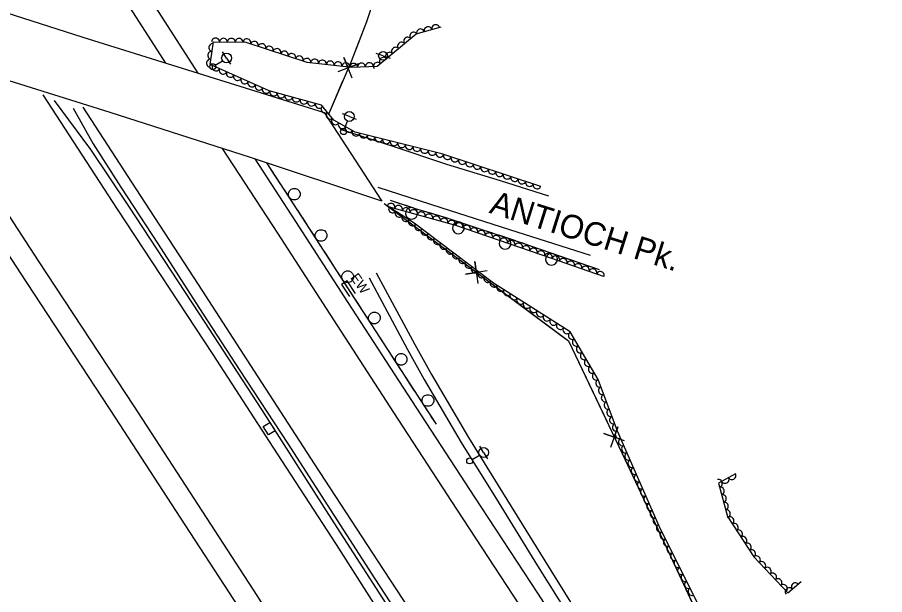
# Model space of a CAD drawing. Extents: x 1746719 to 1766531, y 631721 to 662391.
# Drawn here: x 1758988.5 to 1759429.7, y 642813.8 to 643107.3 of the extents above; entities that cross this region are included whole.
import ezdxf

# ---------------------------------------------------------------- set-up
doc = ezdxf.new("R2010")
doc.units = 0
for name, color, linetype in [('SURVEY - AERIAL SURVEY - Photo Control - Points - Elevations', 7, 'Continuous'), ('SURVEY - AERIAL SURVEY - Photo Control - Points - Numbers', 7, 'Continuous'), ('SURVEY - AERIAL SURVEY - Photo Control with Text', 7, 'Continuous'), ('SURVEY - CENTERLINE - Existing Roads - Development', 7, 'Continuous'), ('SURVEY - CENTERLINE - Existing Roads Curve Text', 7, 'Continuous'), ('SURVEY - CENTERLINE - Existing Roads Text', 7, 'Continuous'), ('SURVEY - CENTERLINE - Preliminary - Development', 7, 'Continuous'), ('SURVEY - CENTERLINE - Preliminary Curve Text', 7, 'Continuous'), ('SURVEY - CONTROL - Points - Numbers', 7, 'Continuous')]:
    doc.layers.add(name, color=color, linetype=linetype)

msp = doc.modelspace()

# ---------------------------------------------------------------- linework, layer by layer
at = {"layer": 'SURVEY - AERIAL SURVEY - Photo Control - Points - Elevations'}
for points in [[(1758528.06, 643931.93), (1758563.85, 643876.61), (1758601.12, 643819.25), (1758634.52, 643767.49), (1758665.16, 643720.35), (1758703.51, 643661.29), (1758738.55, 643607.32), (1758780.47, 643542.02), (1758810.94, 643495.12), (1758838.28, 643453.17), (1758866.99, 643408.66), (1758892.36, 643369.61), (1758923.55, 643321.11), (1758957.87, 643268.54), (1758994.04, 643213.01), (1759028.02, 643160.29), (1759080.26, 643078.92)], [(1758518.82, 643925.96), (1758554.62, 643870.63), (1758591.89, 643813.27), (1758625.29, 643761.51), (1758655.94, 643714.35), (1758694.29, 643655.3), (1758729.31, 643601.35), (1758771.23, 643536.05), (1758801.72, 643489.13), (1758829.05, 643447.19), (1758857.76, 643402.68), (1758883.12, 643363.64), (1758914.32, 643315.13), (1758948.66, 643262.53), (1758984.81, 643207.03), (1759018.77, 643154.33), (1759063.92, 643084.02)], [(1758911.54, 643097.78), (1758989.93, 642977.45), (1759038.48, 642903.58), (1759068.99, 642856.62), (1759101.06, 642807.38), (1759127.09, 642766.38), (1759158.82, 642717.62), (1759188.78, 642671.16), (1759215.73, 642628.82), (1759243.37, 642584.64)], [(1758928.02, 643092.63), (1758999.13, 642983.47), (1759047.68, 642909.6), (1759078.21, 642862.62), (1759110.31, 642813.33), (1759136.34, 642772.33), (1759168.05, 642723.6), (1759198.04, 642677.1), (1759225.03, 642634.69), (1759251.44, 642592.47), (1759258.89, 642580.68)], [(1759001.41, 643067.92), (1759039.3, 643009.76), (1759087.86, 642935.86), (1759118.45, 642888.8), (1759150.69, 642839.29), (1759176.72, 642798.29), (1759208.34, 642749.7), (1759238.46, 642702.99), (1759265.63, 642660.31), (1759292.08, 642618.02), (1759319.51, 642574.62)], [(1759021.72, 643061.55), (1759051.04, 643016.68), (1759080.55, 642971.41), (1759107.16, 642930.21), (1759139.57, 642880.23), (1759171.78, 642830.99), (1759203.62, 642782.41), (1759232.48, 642737.67), (1759263.95, 642689.2), (1759295.27, 642641.6), (1759332.64, 642583.53)], [(1759258.95, 643016.38), (1759234.29, 643024.12), (1759206.97, 643032.5), (1759180.19, 643041.4), (1759152.9, 643050.18)], [(1759092.74, 643040.6), (1759120.81, 642997.54), (1759147.46, 642956.29), (1759179.8, 642906.42), (1759211.94, 642857.29), (1759243.86, 642808.57), (1759272.78, 642763.75), (1759304.12, 642715.46), (1759335.5, 642667.78), (1759373, 642609.52)], [(1759109.35, 643035.26), (1759130.04, 643003.53), (1759156.69, 642962.27), (1759189.01, 642912.43), (1759221.14, 642863.31), (1759253.09, 642814.57), (1759282.01, 642769.72), (1759313.33, 642721.48), (1759344.72, 642673.78), (1759382.25, 642615.47)], [(1759280.06, 642986.24), (1759239.01, 642999.29), (1759204.06, 643010.38), (1759172.11, 643020.76)]]:
    msp.add_lwpolyline(points, dxfattribs=at)
at = {"layer": 'SURVEY - AERIAL SURVEY - Photo Control - Points - Numbers'}
for points in [[(1759007.19, 643064.96), (1759025.66, 643040.03), (1759044.99, 643011.2), (1759080.91, 642956.61), (1759112.63, 642907.86), (1759149.44, 642850.31), (1759187.39, 642791.73), (1759215.17, 642749.46), (1759246.32, 642701.23), (1759270.84, 642663.44), (1759296.65, 642624.73), (1759310.14, 642601.55), (1759323.65, 642577.03)], [(1759016.86, 643061.11), (1759027.02, 643042.95), (1759041.14, 643020.93), (1759060.14, 642992.04), (1759080.88, 642959.71), (1759101.74, 642927.76), (1759125.98, 642890.82), (1759149.43, 642854.16), (1759170.35, 642821.89), (1759192.85, 642787.19), (1759216.64, 642750.69), (1759240.52, 642713.73), (1759263.06, 642678.75), (1759290.15, 642637.06), (1759302.4, 642618.23), (1759316.38, 642598.71), (1759329.6, 642580.54)], [(1759201.66, 642900.4), (1759192.36, 642914.61), (1759160.05, 642964.44), (1759133.4, 643005.71), (1759115.45, 643033.24)], [(1759115.7, 643032.85), (1759115.45, 643033.24)], [(1759120.01, 643026.23), (1759117.45, 643030.17)], [(1759122.58, 643022.3), (1759120.01, 643026.23)], [(1759129.35, 643011.91), (1759124.33, 643019.62)], [(1759178.1, 643014.34), (1759190.9, 643010.16), (1759206.92, 643005.4), (1759244.65, 642992.85), (1759284.43, 642979.03)], [(1759178.1, 643014.34), (1759182.57, 643012.88)], [(1759185.61, 643011.88), (1759190.9, 643010.16), (1759194.39, 643009.12)], [(1759133.67, 643005.29), (1759133.4, 643005.71), (1759131.1, 643009.23)], [(1759197.46, 643008.21), (1759201.96, 643006.87)], [(1759201.96, 643006.87), (1759206.47, 643005.54)], [(1759136.22, 643001.34), (1759133.67, 643005.29)], [(1759209.51, 643004.54), (1759218.24, 643001.64)], [(1759142.94, 642990.93), (1759137.95, 642998.66)], [(1759221.28, 643000.63), (1759225.74, 642999.14)], [(1759225.74, 642999.14), (1759230.2, 642997.66)], [(1759233.23, 642996.65), (1759241.96, 642993.75)], [(1759245, 642992.73), (1759249.44, 642991.19)], [(1759249.44, 642991.19), (1759253.88, 642989.65)], [(1759256.9, 642988.6), (1759265.59, 642985.58)], [(1759147.23, 642984.29), (1759144.68, 642988.24)], [(1759149.78, 642980.34), (1759147.23, 642984.29)], [(1759268.61, 642984.53), (1759273.05, 642982.98)], [(1759273.05, 642982.98), (1759277.49, 642981.44)], [(1759280.51, 642980.39), (1759284.43, 642979.03)], [(1759156.51, 642969.93), (1759151.51, 642977.66)], [(1759160.79, 642963.29), (1759160.05, 642964.44), (1759158.24, 642967.24)], [(1759163.35, 642959.35), (1759160.79, 642963.29)], [(1759170.1, 642948.94), (1759165.09, 642956.66)], [(1759174.4, 642942.32), (1759171.84, 642946.26)], [(1759176.95, 642938.37), (1759174.4, 642942.32)], [(1759183.7, 642927.97), (1759178.7, 642935.69)], [(1759188, 642921.34), (1759185.44, 642925.28)], [(1759190.56, 642917.4), (1759188, 642921.34)], [(1759197.33, 642907.01), (1759192.36, 642914.61), (1759192.3, 642914.71)], [(1759201.66, 642900.4), (1759199.09, 642904.34)]]:
    msp.add_lwpolyline(points, dxfattribs=at)
for centre, start, end in [((1759129.38, 643017.36), 326.3727, 326.3587), ((1759189.01, 643007.62), 185.178, 185.164), ((1759212.89, 643000.26), 184.8727, 184.8588), ((1759142.99, 642996.38), 326.1247, 326.1107), ((1759236.61, 642992.37), 184.8727, 184.8588), ((1759260.22, 642984.27), 184.1027, 184.0887), ((1759156.55, 642975.38), 326.1247, 326.1107), ((1759170.14, 642954.4), 326.2333, 326.2193), ((1759183.74, 642933.42), 326.2333, 326.2193), ((1759197.35, 642912.47), 326.4591, 326.4451)]:
    msp.add_arc(centre, 3, start, end, dxfattribs=at)
at = {"layer": 'SURVEY - AERIAL SURVEY - Photo Control with Text'}
for points in [[(1759254.76, 643021.35), (1759204.49, 643037.81), (1759160.4, 643048.88), (1759149.45, 643055.05), (1759143.16, 643062.68), (1759116.67, 643069.84), (1759086.54, 643083.23), (1759088.27, 643094.82), (1759104.79, 643094.58), (1759135.7, 643084.53), (1759158.72, 643081.94), (1759171.48, 643082.41), (1759191.44, 643098.92), (1759204.1, 643102.39)], [(1759429.72, 642645.24), (1759395.51, 642683.74), (1759381.02, 642706.41), (1759361.81, 642748.55), (1759341.14, 642796.23), (1759314.98, 642848.6), (1759293.78, 642896.97), (1759283.92, 642923.22), (1759269.67, 642947.31), (1759230.71, 642972.18), (1759190.33, 643002.56), (1759177.19, 643011.19), (1759211.36, 643001.58), (1759260.17, 642984.88), (1759286.57, 642975.65)], [(1759353.87, 642875.13), (1759345.13, 642870.47), (1759349.69, 642853.56), (1759363.17, 642833.03), (1759380.39, 642814.76), (1759387.28, 642820.39)]]:
    msp.add_lwpolyline(points, dxfattribs=at)
for centre, major_axis in [((1759201.28, 643101.61), (1.93, 0.53)), ((1759190.06, 643097.78), (1.54, 1.27)), ((1759193.57, 643099.5), (1.93, 0.53)), ((1759197.42, 643100.56), (1.93, 0.53)), ((1759089.34, 643094.8), (2, -0.03)), ((1759093.34, 643094.74), (2, -0.03)), ((1759097.34, 643094.69), (2, -0.03)), ((1759101.33, 643094.63), (2, -0.03)), ((1759105.31, 643094.41), (1.9, -0.62)), ((1759109.11, 643093.17), (1.9, -0.62)), ((1759183.89, 643092.68), (1.54, 1.27)), ((1759186.97, 643095.23), (1.54, 1.27)), ((1759087.25, 643087.96), (0.3, 1.98)), ((1759087.84, 643091.91), (0.3, 1.98)), ((1759112.92, 643091.94), (1.9, -0.62)), ((1759116.72, 643090.7), (1.9, -0.62)), ((1759120.52, 643089.46), (1.9, -0.62)), ((1759124.33, 643088.23), (1.9, -0.62)), ((1759180.81, 643090.13), (1.54, 1.27)), ((1759086.65, 643084), (0.3, 1.98)), ((1759128.13, 643086.99), (1.9, -0.62)), ((1759131.94, 643085.75), (1.9, -0.62)), ((1759135.74, 643084.53), (1.99, -0.22)), ((1759139.72, 643084.08), (1.99, -0.22)), ((1759143.69, 643083.63), (1.99, -0.22)), ((1759174.65, 643085.03), (1.54, 1.27)), ((1759177.73, 643087.58), (1.54, 1.27)), ((1759089.48, 643081.92), (-1.83, 0.81)), ((1759093.14, 643080.3), (-1.83, 0.81)), ((1759147.67, 643083.18), (1.99, -0.22)), ((1759151.64, 643082.73), (1.99, -0.22)), ((1759155.62, 643082.29), (1.99, -0.22)), ((1759159.6, 643081.97), (2, 0.07)), ((1759163.59, 643082.12), (2, 0.07)), ((1759167.59, 643082.27), (2, 0.07)), ((1759171.56, 643082.48), (1.54, 1.27)), ((1759096.79, 643078.67), (-1.83, 0.81)), ((1759100.45, 643077.05), (-1.83, 0.81)), ((1759104.1, 643075.42), (-1.83, 0.81)), ((1759107.76, 643073.8), (-1.83, 0.81)), ((1759111.41, 643072.17), (-1.83, 0.81)), ((1759115.07, 643070.55), (-1.83, 0.81)), ((1759118.84, 643069.25), (-1.93, 0.52)), ((1759122.7, 643068.21), (-1.93, 0.52)), ((1759126.56, 643067.16), (-1.93, 0.52)), ((1759130.42, 643066.12), (-1.93, 0.52)), ((1759134.29, 643065.08), (-1.93, 0.52)), ((1759138.15, 643064.03), (-1.93, 0.52)), ((1759142.01, 643062.99), (-1.93, 0.52)), ((1759144.95, 643060.51), (-1.27, 1.54)), ((1759147.49, 643057.42), (-1.27, 1.54)), ((1759150.25, 643054.6), (-1.74, 0.98)), ((1759153.74, 643052.63), (-1.74, 0.98)), ((1759157.22, 643050.67), (-1.74, 0.98)), ((1759160.74, 643048.79), (-1.94, 0.49)), ((1759164.62, 643047.82), (-1.94, 0.49)), ((1759168.5, 643046.84), (-1.94, 0.49)), ((1759172.38, 643045.87), (-1.94, 0.49)), ((1759176.26, 643044.9), (-1.94, 0.49)), ((1759180.14, 643043.92), (-1.94, 0.49)), ((1759184.02, 643042.95), (-1.94, 0.49)), ((1759187.9, 643041.98), (-1.94, 0.49)), ((1759191.78, 643041), (-1.94, 0.49)), ((1759195.66, 643040.03), (-1.94, 0.49)), ((1759199.54, 643039.05), (-1.94, 0.49)), ((1759203.42, 643038.08), (-1.94, 0.49)), ((1759207.24, 643036.91), (-1.9, 0.62)), ((1759211.04, 643035.67), (-1.9, 0.62)), ((1759214.84, 643034.42), (-1.9, 0.62)), ((1759218.64, 643033.18), (-1.9, 0.62)), ((1759222.44, 643031.93), (-1.9, 0.62)), ((1759226.25, 643030.69), (-1.9, 0.62)), ((1759230.05, 643029.44), (-1.9, 0.62)), ((1759233.85, 643028.2), (-1.9, 0.62)), ((1759237.65, 643026.95), (-1.9, 0.62)), ((1759241.45, 643025.71), (-1.9, 0.62)), ((1759245.25, 643024.47), (-1.9, 0.62)), ((1759249.05, 643023.22), (-1.9, 0.62)), ((1759252.86, 643021.98), (-1.9, 0.62)), ((1759178.59, 643010.8), (1.93, -0.54)), ((1759179.31, 643009.8), (-1.67, 1.1)), ((1759182.44, 643009.72), (1.93, -0.54)), ((1759186.29, 643008.63), (1.93, -0.54)), ((1759182.66, 643007.6), (-1.67, 1.1)), ((1759186, 643005.4), (-1.67, 1.1)), ((1759190.14, 643007.55), (1.93, -0.54)), ((1759193.99, 643006.47), (1.93, -0.54)), ((1759197.85, 643005.39), (1.93, -0.54)), ((1759201.7, 643004.3), (1.93, -0.54)), ((1759189.34, 643003.21), (-1.67, 1.1)), ((1759192.58, 643000.87), (-1.6, 1.2)), ((1759205.55, 643003.22), (1.93, -0.54)), ((1759209.4, 643002.14), (1.93, -0.54)), ((1759213.22, 643000.95), (1.89, -0.65)), ((1759217, 642999.66), (1.89, -0.65)), ((1759195.78, 642998.46), (-1.6, 1.2)), ((1759198.98, 642996.06), (-1.6, 1.2)), ((1759220.78, 642998.36), (1.89, -0.65)), ((1759224.57, 642997.06), (1.89, -0.65)), ((1759228.35, 642995.77), (1.89, -0.65)), ((1759202.17, 642993.65), (-1.6, 1.2)), ((1759232.14, 642994.47), (1.89, -0.65)), ((1759235.92, 642993.18), (1.89, -0.65)), ((1759239.71, 642991.88), (1.89, -0.65)), ((1759243.49, 642990.59), (1.89, -0.65)), ((1759205.37, 642991.25), (-1.6, 1.2)), ((1759208.57, 642988.84), (-1.6, 1.2)), ((1759247.28, 642989.29), (1.89, -0.65)), ((1759251.06, 642987.99), (1.89, -0.65)), ((1759254.84, 642986.7), (1.89, -0.65)), ((1759211.76, 642986.44), (-1.6, 1.2)), ((1759214.96, 642984.03), (-1.6, 1.2)), ((1759258.63, 642985.4), (1.89, -0.65)), ((1759262.41, 642984.09), (1.89, -0.66)), ((1759266.18, 642982.77), (1.89, -0.66)), ((1759218.16, 642981.63), (-1.6, 1.2)), ((1759221.35, 642979.22), (-1.6, 1.2)), ((1759269.96, 642981.46), (1.89, -0.66)), ((1759273.74, 642980.14), (1.89, -0.66)), ((1759277.51, 642978.82), (1.89, -0.66)), ((1759281.29, 642977.5), (1.89, -0.66)), ((1759224.55, 642976.82), (-1.6, 1.2)), ((1759227.75, 642974.41), (-1.6, 1.2)), ((1759285.07, 642976.18), (1.89, -0.66)), ((1759230.95, 642972.03), (-1.69, 1.08)), ((1759234.33, 642969.87), (-1.69, 1.08)), ((1759237.7, 642967.72), (-1.69, 1.08)), ((1759241.07, 642965.57), (-1.69, 1.08)), ((1759244.44, 642963.42), (-1.69, 1.08)), ((1759247.81, 642961.26), (-1.69, 1.08)), ((1759251.18, 642959.11), (-1.69, 1.08)), ((1759254.55, 642956.96), (-1.69, 1.08)), ((1759257.92, 642954.81), (-1.69, 1.08)), ((1759261.3, 642952.65), (-1.69, 1.08)), ((1759264.67, 642950.5), (-1.69, 1.08)), ((1759268.04, 642948.35), (-1.69, 1.08)), ((1759270.72, 642945.53), (-1.02, 1.72)), ((1759272.76, 642942.09), (-1.02, 1.72)), ((1759274.8, 642938.64), (-1.02, 1.72)), ((1759276.83, 642935.2), (-1.02, 1.72)), ((1759278.87, 642931.76), (-1.02, 1.72)), ((1759280.91, 642928.32), (-1.02, 1.72)), ((1759282.94, 642924.87), (-1.02, 1.72)), ((1759284.65, 642921.27), (-0.7, 1.87)), ((1759286.06, 642917.53), (-0.7, 1.87)), ((1759287.46, 642913.78), (-0.7, 1.87)), ((1759288.87, 642910.04), (-0.7, 1.87)), ((1759290.27, 642906.29), (-0.7, 1.87)), ((1759291.68, 642902.55), (-0.7, 1.87)), ((1759293.09, 642898.8), (-0.7, 1.87)), ((1759294.59, 642895.1), (-0.8, 1.83)), ((1759296.2, 642891.44), (-0.8, 1.83)), ((1759297.81, 642887.77), (-0.8, 1.83)), ((1759299.41, 642884.11), (-0.8, 1.83)), ((1759301.02, 642880.45), (-0.8, 1.83)), ((1759302.63, 642876.78), (-0.8, 1.83)), ((1759304.23, 642873.12), (-0.8, 1.83)), ((1759352.1, 642874.19), (-1.76, -0.94)), ((1759305.84, 642869.46), (-0.8, 1.83)), ((1759345.16, 642870.37), (0.52, -1.93)), ((1759348.57, 642872.3), (-1.76, -0.94)), ((1759307.44, 642865.79), (-0.8, 1.83)), ((1759346.2, 642866.51), (0.52, -1.93)), ((1759347.24, 642862.64), (0.52, -1.93)), ((1759309.05, 642862.13), (-0.8, 1.83)), ((1759348.28, 642858.78), (0.52, -1.93)), ((1759310.66, 642858.47), (-0.8, 1.83)), ((1759312.26, 642854.8), (-0.8, 1.83)), ((1759349.32, 642854.92), (0.52, -1.93)), ((1759313.87, 642851.14), (-0.8, 1.83)), ((1759351.11, 642851.39), (1.1, -1.67)), ((1759315.53, 642847.5), (-0.89, 1.79)), ((1759353.3, 642848.05), (1.1, -1.67)), ((1759317.32, 642843.93), (-0.89, 1.79)), ((1759355.5, 642844.71), (1.1, -1.67)), ((1759357.7, 642841.36), (1.1, -1.67)), ((1759319.11, 642840.35), (-0.89, 1.79)), ((1759320.89, 642836.77), (-0.89, 1.79)), ((1759359.89, 642838.02), (1.1, -1.67)), ((1759322.68, 642833.19), (-0.89, 1.79)), ((1759362.09, 642834.67), (1.1, -1.67)), ((1759324.47, 642829.61), (-0.89, 1.79)), ((1759364.56, 642831.55), (1.37, -1.46)), ((1759367.3, 642828.64), (1.37, -1.46)), ((1759326.25, 642826.03), (-0.89, 1.79)), ((1759370.05, 642825.73), (1.37, -1.46)), ((1759328.04, 642822.45), (-0.89, 1.79)), ((1759329.83, 642818.88), (-0.89, 1.79)), ((1759372.79, 642822.82), (1.37, -1.46)), ((1759375.54, 642819.91), (1.37, -1.46)), ((1759331.62, 642815.3), (-0.89, 1.79)), ((1759378.28, 642817), (1.37, -1.46)), ((1759381.1, 642815.34), (1.55, 1.27)), ((1759384.2, 642817.87), (1.55, 1.27))]:
    msp.add_ellipse(centre, major_axis=major_axis, ratio=0.940188, start_param=0, end_param=3.141593, dxfattribs=at)
at = {"layer": 'SURVEY - CENTERLINE - Existing Roads - Development'}
for p, q in [((1759094.92, 643086.56), (1759092.93, 643089.74)), ((1759094.92, 643086.56), (1759096.91, 643083.38)), ((1759174.55, 643087.67), (1759171, 643088.87)), ((1759174.55, 643087.67), (1759178.11, 643086.47)), ((1759089.19, 643082.98), (1759092.8, 643085.23)), ((1759157.39, 643056.85), (1759153.89, 643058.19)), ((1759154.97, 643050.55), (1759156.49, 643054.51)), ((1759157.39, 643056.85), (1759160.89, 643055.5)), ((1759225.68, 642886.04), (1759223.74, 642889.25)), ((1759219.9, 642882.54), (1759223.54, 642884.74)), ((1759225.68, 642886.04), (1759227.62, 642882.83))]:
    msp.add_line(p, q, dxfattribs=at)
for centre, radius in [((1759174.55, 643087.67), 2.25), ((1759094.92, 643086.56), 2.5), ((1759087.92, 643082.18), 1.5), ((1759157.39, 643056.85), 2.5), ((1759154.43, 643049.15), 1.5), ((1759225.68, 642886.04), 2.5), ((1759218.62, 642881.77), 1.5)]:
    msp.add_circle(centre, radius, dxfattribs=at)
at = {"layer": 'SURVEY - CENTERLINE - Existing Roads Curve Text'}
for points in [[(1758597.61, 643977.01), (1758617.39, 643945.88), (1758662.34, 643875.34), (1758704.61, 643809.95), (1758741.93, 643752.08), (1758778.03, 643696.12), (1758822.35, 643623.21), (1758848.54, 643583.5), (1758881.82, 643532.03), (1758922.45, 643468.73), (1758955.21, 643418.24), (1758991.22, 643365.93), (1759032.86, 643305.85), (1759060.34, 643262.49), (1759087.59, 643224.61), (1759129.75, 643170.02), (1759169.86, 643116.48), (1759166.15, 643104.96), (1759158.27, 643084.9), (1759146.54, 643057.47)], [(1759157.03, 643133.61), (1759169.86, 643116.48), (1759166.15, 643104.96), (1759160.12, 643089.61)], [(1759158.89, 643076.43), (1759154.64, 643086.84), (1759156.75, 643081.59), (1759162, 643083.7), (1759151.54, 643079.58)], [(1759153.93, 643074.75), (1759146.54, 643057.47)], [(1759175.04, 643012.71), (1759268.8, 642942.78), (1759296.24, 642885.55), (1759318.6, 642838.12), (1759343.92, 642783.7)], [(1759175.04, 643012.71), (1759215.12, 642982.82)], [(1759227.55, 642978.41), (1759216.44, 642976.72), (1759222.04, 642977.53), (1759221.22, 642983.13), (1759222.77, 642972)], [(1759228.03, 642973.19), (1759265.22, 642945.45)], [(1759265.22, 642945.45), (1759268.8, 642942.78), (1759288.49, 642901.72)], [(1759297.45, 642892.04), (1759286.82, 642895.71), (1759292.16, 642893.83), (1759294.04, 642899.17), (1759290.24, 642888.58)], [(1759295.45, 642887.2), (1759296.24, 642885.55), (1759315.24, 642845.24)], [(1759315.24, 642845.24), (1759318.6, 642838.12), (1759336.37, 642799.92)]]:
    msp.add_lwpolyline(points, dxfattribs=at)
at = {"layer": 'SURVEY - CENTERLINE - Existing Roads Text'}
for p, q in [((1758958.7, 643117.48), (1759021.87, 643097.13)), ((1759021.87, 643097.13), (1759144.64, 643058.85)), ((1759035.75, 643058.81), (1758969.11, 643079.78)), ((1759107.13, 643036), (1759035.75, 643058.81)), ((1759144.64, 643058.85), (1759173.93, 643013.81)), ((1759173.93, 643013.81), (1759107.13, 643036))]:
    msp.add_line(p, q, dxfattribs=at)
for points in [[(1759171.03, 642977.35), (1759190.67, 642940.94), (1759199.14, 642925.71), (1759217.98, 642893.66), (1759235.36, 642865.74), (1759256.78, 642830.98), (1759272.94, 642805.07), (1759287.45, 642781.38), (1759305.2, 642753.34), (1759326.51, 642719.84), (1759350.08, 642683.57), (1759375.26, 642644.36), (1759391.59, 642619.53)], [(1759160.6, 642966.9), (1759156.23, 642973.27), (1759153.41, 642971.51), (1759157.52, 642965.31)], [(1759167.4, 642974.81), (1759187.04, 642938.4), (1759195.51, 642923.17), (1759214.35, 642891.12), (1759231.73, 642863.2), (1759253.15, 642828.44), (1759269.31, 642802.53), (1759283.82, 642778.84), (1759301.57, 642750.81), (1759322.88, 642717.31), (1759346.45, 642681.03), (1759371.63, 642641.82), (1759387.95, 642616.99)]]:
    msp.add_lwpolyline(points, dxfattribs=at)
at = {"layer": 'SURVEY - CENTERLINE - Preliminary Curve Text'}
msp.add_line((1759116.63, 642898.14), (1759116.63, 642898.14), dxfattribs=at)
msp.add_lwpolyline([(1759113.6, 642899.19), (1759116.99, 642901.32), (1759119.65, 642897.09), (1759116.27, 642894.96), (1759113.6, 642899.19)], dxfattribs=at)

# ---------------------------------------------------------------- texts
at = {"layer": 'SURVEY - CENTERLINE - Preliminary - Development'}
msp.add_text('EW', height=5, rotation=305.2408, dxfattribs=at).set_placement((1759157.67, 642974.94))
at = {"layer": 'SURVEY - CONTROL - Points - Numbers'}
msp.add_text('ANTIOCH Pk.', height=12, rotation=342.5328, dxfattribs=at).set_placement((1759228.08, 643007.98))

doc.saveas('drawing.dxf')
